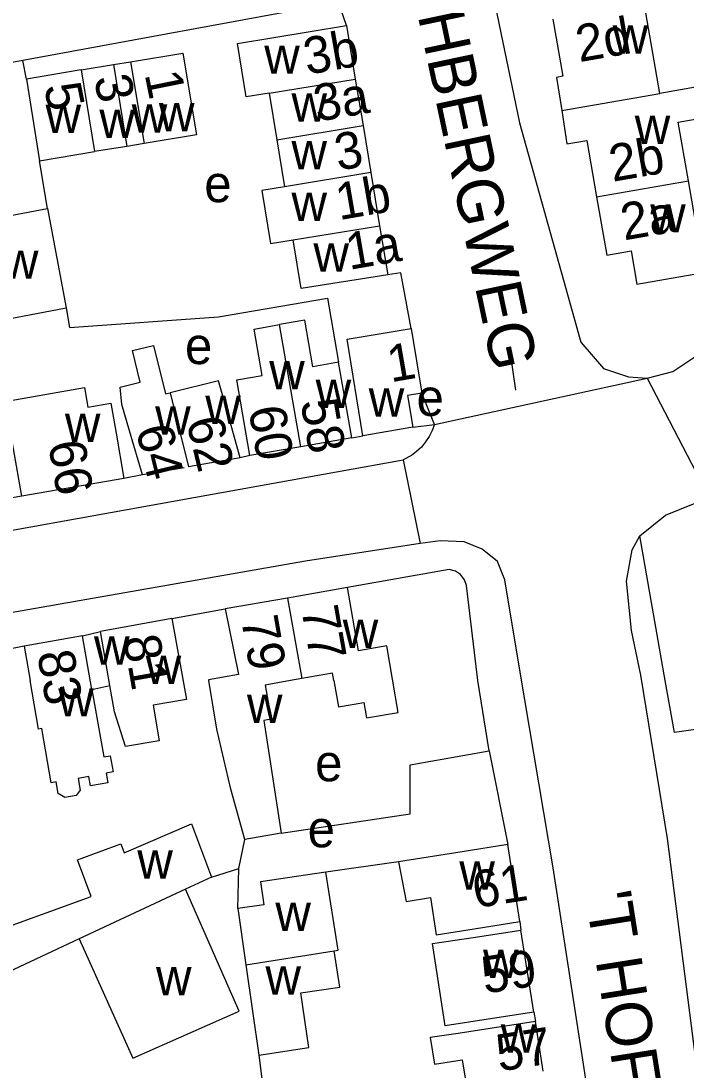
# Model space of a CAD drawing. Extents: x 162883 to 165538, y 383986 to 385172.
# Drawn here: x 164216 to 164288.3, y 384457.6 to 384571.7 of the extents above; entities that cross this region are included whole.
import ezdxf

# ---------------------------------------------------------------- set-up
doc = ezdxf.new("R2010")
doc.units = 0
for name, color, linetype in [('BLT_Basislijn', 7, 'Continuous'), ('BLT_Bebouwing', 7, 'Continuous'), ('BLT_Centroide', 7, 'Continuous'), ('BLT_Huisnummer', 7, 'Continuous'), ('BLT_Huisnummer_ tussenligend', 7, 'Continuous'), ('BLT_Huisnummer_reeks', 7, 'Continuous'), ('BLT_Onderdoorgang_en_onderverdeling', 7, 'Continuous'), ('BLT_Onderverdeling_panden', 7, 'Continuous'), ('BLT_Straatnaam', 7, 'Continuous'), ('BLT_Vlakafsluiter', 7, 'Continuous')]:
    doc.layers.add(name, color=color, linetype=linetype)

msp = doc.modelspace()

# ---------------------------------------------------------------- linework, layer by layer
at = {"layer": 'BLT_Basislijn'}
for p, q in [((164251.35, 384571.17), (164250.47, 384573.67)), ((164216.55, 384565.36), (164216.18, 384567.37)), ((164218.83, 384551.3), (164217.99, 384556.49)), ((164269.2, 384535.3), (164269.72, 384531.55)), ((164260.92, 384527.84), (164259.55, 384531.22)), ((164258.56, 384527.52), (164260.92, 384527.84)), ((164251.92, 384526.38), (164253.14, 384526.6)), ((164240.85, 384524.45), (164239.81, 384524.19)), ((164177.77, 384509.68), (164257.53, 384523.99)), ((164229.16, 384522.34), (164227.16, 384521.97)), ((164216.04, 384520.04), (164215.02, 384519.85)), ((164286.01, 384500), (164283.23, 384515.73)), ((164262.51, 384512.08), (164251.47, 384510.11)), ((164232.37, 384506.75), (164238.16, 384507.8)), ((164216.31, 384503.73), (164212.88, 384503.06)), ((164266.85, 384492.38), (164265.64, 384500)), ((164266.85, 384492.38), (164268.88, 384482.18)), ((164257.02, 384480.32), (164249.1, 384479.2)), ((164239.53, 384475.24), (164239.65, 384479.58)), ((164270.19, 384473.82), (164270.31, 384472.9)), ((164271.71, 384463.99), (164271.9, 384462.97))]:
    msp.add_line(p, q, dxfattribs=at)
for points in [[(164264.67, 384587.17), (164270.15, 384560.59), (164276.83, 384536.76), (164279.31, 384533.9), (164282.01, 384533.02), (164284.05, 384532.85)], [(164250.47, 384573.67), (164216.18, 384567.37)], [(164216.18, 384567.37), (164194.67, 384563.42)], [(164258.38, 384538.24), (164257.25, 384544.31), (164255.83, 384544.09)], [(164284.05, 384532.85), (164286.85, 384533.58), (164302.15, 384543.79)], [(164220.86, 384540.49), (164221.25, 384538.38), (164237.43, 384539.52), (164249.29, 384541.57), (164250.49, 384534.59)], [(164260.92, 384527.84), (164260.67, 384527.17), (164260.35, 384526.53), (164259.95, 384525.93), (164259.49, 384525.38), (164258.98, 384524.88), (164258.41, 384524.44), (164257.53, 384523.99)], [(164283.23, 384515.73), (164286.02, 384517.99), (164290.78, 384519.9)], [(164283.58, 384416.59), (164273.81, 384479.64), (164270.25, 384500.9), (164268.57, 384510.96), (164267.77, 384512.93), (164266.12, 384514.27), (164264.16, 384515.09), (164261.54, 384515.19), (164259.36, 384514.9)], [(164300.94, 384409.91), (164297.77, 384409.92), (164295.9, 384411.19), (164295.12, 384413.33), (164293.49, 384426.14), (164290.57, 384449.19), (164286.27, 384482.86), (164283.36, 384500.58), (164282.34, 384505.46), (164281.79, 384510.79), (164282.4, 384514.2), (164283.23, 384515.73)], [(164259.36, 384514.9), (164246.89, 384512.98), (164214.63, 384507.32), (164195.63, 384504), (164166.27, 384498.87), (164153.15, 384496.57), (164133.08, 384493.12), (164119.1, 384490.68), (164110.6, 384488.4), (164108.86, 384487.76), (164097.58, 384481.96), (164089.42, 384477.7), (164083.48, 384473.7), (164079.44, 384470.87), (164074.54, 384465.16), (164073.61, 384463.51), (164073.36, 384461.62), (164073.79, 384459.86), (164077.68, 384451.03)], [(164265.64, 384500), (164264.41, 384510.33), (164264.2, 384510.96), (164263.75, 384511.52), (164263.22, 384511.88), (164262.51, 384512.08)], [(164292.61, 384495.15), (164292.39, 384495.11), (164287.01, 384494.35), (164286.01, 384500)], [(164244.25, 384483.43), (164258.28, 384485.51), (164258.28, 384490.85), (164266.85, 384492.38)], [(164239.65, 384479.58), (164240.29, 384482.73)], [(164236.67, 384478.66), (164239.65, 384479.58)], [(164241.82, 384459.3), (164243.68, 384444.62), (164245.99, 384430.1), (164240.55, 384423.1), (164228.61, 384411.2)]]:
    msp.add_lwpolyline(points, dxfattribs=at)
at = {"layer": 'BLT_Bebouwing'}
for p, q in [((164285.43, 384563.8), (164283.72, 384573.6)), ((164251.35, 384571.17), (164252.31, 384565.35)), ((164252.31, 384565.35), (164253.15, 384560.3)), ((164242.93, 384563.84), (164243.77, 384558.75)), ((164253.15, 384560.3), (164253.99, 384555.21)), ((164243.77, 384558.75), (164244.61, 384553.66)), ((164253.99, 384555.21), (164254.95, 384549.4)), ((164254.95, 384549.4), (164255.83, 384544.09)), ((164258.38, 384538.24), (164259.55, 384531.22)), ((164251.92, 384526.38), (164250.49, 384534.59)), ((164258.56, 384527.52), (164253.14, 384526.6)), ((164246.39, 384525.41), (164240.85, 384524.45)), ((164251.92, 384526.38), (164246.39, 384525.41)), ((164239.81, 384524.19), (164234.16, 384523.21)), ((164233.71, 384523.13), (164229.16, 384522.34)), ((164227.16, 384521.97), (164216.04, 384520.04)), ((164251.47, 384510.11), (164244.93, 384508.97)), ((164244.93, 384508.97), (164238.16, 384507.8)), ((164232.37, 384506.75), (164224.59, 384505.32)), ((164222.66, 384504.85), (164216.31, 384503.73)), ((164222.66, 384504.85), (164224.59, 384505.32)), ((164216.31, 384503.73), (164216.96, 384500)), ((164246.48, 384500.22), (164245.25, 384500)), ((164223.68, 384499.04), (164225.62, 384499.46)), ((164227.18, 384481.28), (164234.49, 384484.44)), ((164234.49, 384484.44), (164236.67, 384478.66)), ((164222.11, 384480.51), (164226.81, 384482.28)), ((164226.81, 384482.28), (164227.18, 384481.28)), ((164270.19, 384473.82), (164268.88, 384482.18)), ((164223.58, 384476.55), (164222.11, 384480.51)), ((164236.67, 384478.66), (164233.85, 384477.34)), ((164212.9, 384472.68), (164223.58, 384476.55)), ((164271.71, 384463.99), (164270.31, 384472.9)), ((164222.29, 384471.93), (164208.68, 384465.56)), ((164240.41, 384469.1), (164241.13, 384464.1)), ((164241.13, 384464.1), (164241.82, 384459.3)), ((164272.74, 384457.56), (164271.9, 384462.97))]:
    msp.add_line(p, q, dxfattribs=at)
for points in [[(164242.93, 384563.84), (164240.44, 384563.44), (164239.51, 384569.23), (164251.35, 384571.17)], [(164273.8, 384571.86), (164274.88, 384565.66), (164274.19, 384565.54), (164274.75, 384561.93)], [(164227.88, 384567.24), (164233.55, 384568.18), (164235.03, 384559.3), (164229.35, 384558.36)], [(164222.51, 384566.35), (164226.03, 384566.93)], [(164226.03, 384566.93), (164227.88, 384567.24)], [(164222.51, 384566.35), (164216.55, 384565.36)], [(164216.55, 384565.36), (164217.99, 384556.49)], [(164288.53, 384554.29), (164287.41, 384560.68), (164292.15, 384561.51), (164291.56, 384564.87), (164285.43, 384563.8)], [(164274.75, 384561.93), (164275.31, 384558.33), (164277.48, 384558.7), (164278.55, 384552.55)], [(164217.99, 384556.49), (164223.97, 384557.48)], [(164227.46, 384558.05), (164223.97, 384557.48)], [(164229.35, 384558.36), (164227.46, 384558.05)], [(164278.55, 384552.55), (164279.65, 384546.24), (164282.29, 384546.7), (164282.92, 384543.06), (164289.98, 384544.29), (164290.04, 384543.94), (164293.17, 384544.49), (164292.11, 384550.59), (164289.26, 384550.1), (164288.53, 384554.29)], [(164244.61, 384553.66), (164242.16, 384553.25), (164243.09, 384547.48), (164245.57, 384547.88)], [(164213.45, 384550.29), (164218.83, 384551.3)], [(164218.83, 384551.3), (164220.86, 384540.49)], [(164255.83, 384544.09), (164246.44, 384542.59), (164245.57, 384547.88)], [(164211.52, 384538.73), (164220.86, 384540.49)], [(164250.49, 384534.59), (164247.71, 384534.11), (164246.83, 384539.16), (164244.08, 384538.68)], [(164240.85, 384524.45), (164239.42, 384532.67), (164242.18, 384533.15), (164241.31, 384538.2), (164244.08, 384538.68)], [(164253.14, 384526.6), (164251.41, 384537.1), (164258.38, 384538.24)], [(164229.16, 384522.34), (164227.76, 384527.14), (164226.92, 384529.99), (164226.74, 384531.9), (164228.93, 384532.43), (164228.1, 384535.85), (164230.37, 384536.41), (164231.66, 384531.15), (164232.18, 384531.28)], [(164239.81, 384524.19), (164238.45, 384529.01), (164237.44, 384532.57), (164232.18, 384531.28)], [(164216.04, 384520.04), (164214.24, 384530.34), (164222.86, 384531.83), (164223.23, 384529.7), (164225.74, 384530.14), (164226.31, 384526.9), (164227.16, 384521.97)], [(164259.55, 384531.22), (164257.99, 384530.96), (164258.56, 384527.52)], [(164255.74, 384503.76), (164252.65, 384503.23), (164251.47, 384510.11)], [(164238.16, 384507.8), (164239.6, 384500.68), (164236.35, 384500.1), (164236.37, 384500)], [(164232.37, 384506.75), (164233.94, 384497.95), (164230.32, 384497.32), (164230.99, 384493.46), (164227.33, 384492.83), (164226.13, 384496.6), (164225.62, 384499.46)], [(164249.98, 384500), (164250.47, 384497.14), (164253.24, 384497.62), (164253.52, 384495.94), (164256.98, 384496.54), (164255.74, 384503.76)], [(164249.98, 384500), (164249.84, 384500.81), (164246.48, 384500.22)], [(164223.68, 384499.04), (164224.98, 384491.7), (164225.67, 384491.82), (164225.98, 384490.07), (164225.22, 384489.93), (164225.4, 384488.88), (164223.51, 384488.55), (164223.33, 384489.57), (164222.18, 384489.37), (164222.4, 384488.1), (164221.97, 384487.5), (164220.73, 384487.29), (164220.02, 384487.74), (164219.8, 384488.99), (164219.24, 384488.89), (164218.22, 384494.8), (164217.88, 384494.74), (164217.19, 384498.73), (164216.96, 384500)], [(164238.77, 384488.21), (164237.27, 384494.72), (164236.37, 384500)], [(164245.25, 384500), (164242.52, 384499.51), (164243.15, 384495.82), (164242.38, 384495.68), (164244.25, 384483.43)], [(164240.29, 384482.73), (164238.77, 384488.21)], [(164244.25, 384483.43), (164240.29, 384482.73)], [(164268.88, 384482.18), (164263.94, 384481.41), (164257.02, 384480.32)], [(164257.02, 384480.32), (164257.83, 384476.01), (164260.47, 384476.42), (164261.1, 384472.39), (164265.25, 384473.04), (164270.19, 384473.82)], [(164249.1, 384479.2), (164242.02, 384478.12), (164242.36, 384475.64), (164239.53, 384475.24)], [(164250.03, 384470.65), (164250.44, 384470.72), (164249.1, 384479.2)], [(164222.29, 384471.93), (164228.14, 384458.96), (164239.69, 384464.1), (164233.85, 384477.34)], [(164239.53, 384475.24), (164240.41, 384469.1)], [(164271.71, 384463.99), (164266.77, 384463.21), (164262.09, 384462.48), (164260.7, 384471.42), (164265.37, 384472.13), (164270.31, 384472.9)], [(164241.82, 384459.3), (164247.26, 384460.12), (164246.39, 384466.09), (164250.62, 384466.69), (164250.03, 384470.65)], [(164271.9, 384462.97), (164266.96, 384462.19), (164263.49, 384461.65), (164260.44, 384461.22), (164260.93, 384458.33), (164263.94, 384458.8), (164264.35, 384456.15)]]:
    msp.add_lwpolyline(points, dxfattribs=at)
at = {"layer": 'BLT_Onderdoorgang_en_onderverdeling'}
msp.add_line((164226.03, 384566.93), (164227.46, 384558.05), dxfattribs=at)
at = {"layer": 'BLT_Onderverdeling_panden'}
for p, q in [((164227.88, 384567.24), (164229.35, 384558.36)), ((164222.51, 384566.35), (164223.97, 384557.48)), ((164242.93, 384563.84), (164252.31, 384565.35)), ((164274.75, 384561.93), (164285.43, 384563.8)), ((164243.77, 384558.75), (164253.15, 384560.3)), ((164253.99, 384555.21), (164244.61, 384553.66)), ((164278.55, 384552.55), (164288.53, 384554.29)), ((164245.57, 384547.88), (164254.95, 384549.4)), ((164246.39, 384525.41), (164244.08, 384538.68)), ((164232.18, 384531.28), (164234.16, 384523.21)), ((164244.93, 384508.97), (164246.48, 384500.22)), ((164223.68, 384499.04), (164222.66, 384504.85)), ((164233.85, 384477.34), (164222.29, 384471.93))]:
    msp.add_line(p, q, dxfattribs=at)
for points in [[(164225.62, 384499.46), (164224.59, 384505.32)], [(164240.41, 384469.1), (164250.03, 384470.65)]]:
    msp.add_lwpolyline(points, dxfattribs=at)
at = {"layer": 'BLT_Vlakafsluiter'}
for p, q in [((164260.92, 384527.84), (164284.05, 384532.85)), ((164284.05, 384532.85), (164290.78, 384519.9)), ((164257.53, 384523.99), (164259.36, 384514.9))]:
    msp.add_line(p, q, dxfattribs=at)

# ---------------------------------------------------------------- texts
at = {"layer": 'BLT_Centroide'}
for s, p in [('w', (164280.29, 384568.12)), ('w', (164242.41, 384565.93)), ('w', (164245.37, 384560.74)), ('w', (164218.63, 384559.51)), ('w', (164224.49, 384558.96)), ('w', (164228, 384559.54)), ('w', (164230.96, 384559.68)), ('w', (164282.69, 384558.31)), ('w', (164245.37, 384555.55)), ('e', (164235.89, 384551.98)), ('w', (164245.37, 384549.95)), ('w', (164284.37, 384548.69)), ('w', (164247.76, 384544.43)), ('w', (164214, 384543.66)), ('e', (164233.79, 384534.39)), ('w', (164242.95, 384531.66)), ('w', (164248, 384529.61)), ('w', (164253.77, 384528.69)), ('e', (164258.97, 384528.76)), ('w', (164236, 384527.88)), ('w', (164220.74, 384525.94)), ('w', (164230.55, 384526.73)), ('w', (164250.94, 384503.55)), ('w', (164223.9, 384501.72)), ('w', (164229.52, 384499.64)), ('w', (164220.01, 384496.1)), ('w', (164240.53, 384495.41)), ('e', (164247.94, 384489.06)), ('e', (164247.13, 384481.89)), ('w', (164228.61, 384478.48)), ('w', (164263.62, 384477.28)), ('w', (164243.62, 384472.81)), ('w', (164266.2, 384467.69)), ('w', (164230.64, 384465.81)), ('w', (164242.54, 384465.89)), ('w', (164268.12, 384459.59))]:
    msp.add_text(s, height=4, dxfattribs=at).set_placement(p)
at = {"layer": 'BLT_Huisnummer'}
for s, rotation, p in [('3b', 9.8562, (164247.06, 384565.82)), ('1', 281.3986, (164229.4, 384565.9)), ('5', 281.3986, (164218.45, 384564.59)), ('3a', 9.8562, (164248.16, 384560.71)), ('3', 9.8562, (164250.44, 384555.39)), ('1b', 9.8562, (164250.55, 384550.02)), ('2a', 9.8754, (164281.53, 384547.82)), ('1a', 9.8562, (164251.65, 384544.62)), ('1', 9.8562, (164256.16, 384532.4)), ('58', 279.8569, (164246.34, 384530.32)), ('60', 279.8569, (164240.68, 384529.55)), ('64', 283.7552, (164228.41, 384527.33)), ('62', 283.7552, (164233.9, 384528.21)), ('66', 279.8675, (164218.9, 384525.78)), ('77', 280.0095, (164246.42, 384507.81)), ('79', 280.0131, (164239.87, 384506.72)), ('81', 279.9974, (164227.05, 384504.65)), ('83', 280.1224, (164217.7, 384502.98)), ('61', 8.9178, (164265.37, 384475.27)), ('57', 8.9141, (164267.96, 384457.52))]:
    msp.add_text(s, height=4, rotation=rotation, dxfattribs=at).set_placement(p)
at = {"layer": 'BLT_Huisnummer_ tussenligend'}
for s, rotation, p in [('2d', 9.8853, (164276.66, 384567.19)), ('3', 281.3986, (164223.88, 384565.48)), ('2b', 9.8786, (164280.28, 384554.19))]:
    msp.add_text(s, height=4, rotation=rotation, dxfattribs=at).set_placement(p)
at = {"layer": 'BLT_Huisnummer_reeks'}
msp.add_text('59', height=4, rotation=8.9154, dxfattribs=at).set_placement((164266.36, 384465.97))
at = {"layer": 'BLT_Straatnaam'}
for s, rotation, p in [('MUSCHBERGWEG', 281.9221, (164255.02, 384591.56)), ("'T HOFKE", 279.0311, (164277.29, 384476.74))]:
    msp.add_text(s, height=5, rotation=rotation, dxfattribs=at).set_placement(p)

doc.saveas('drawing.dxf')
